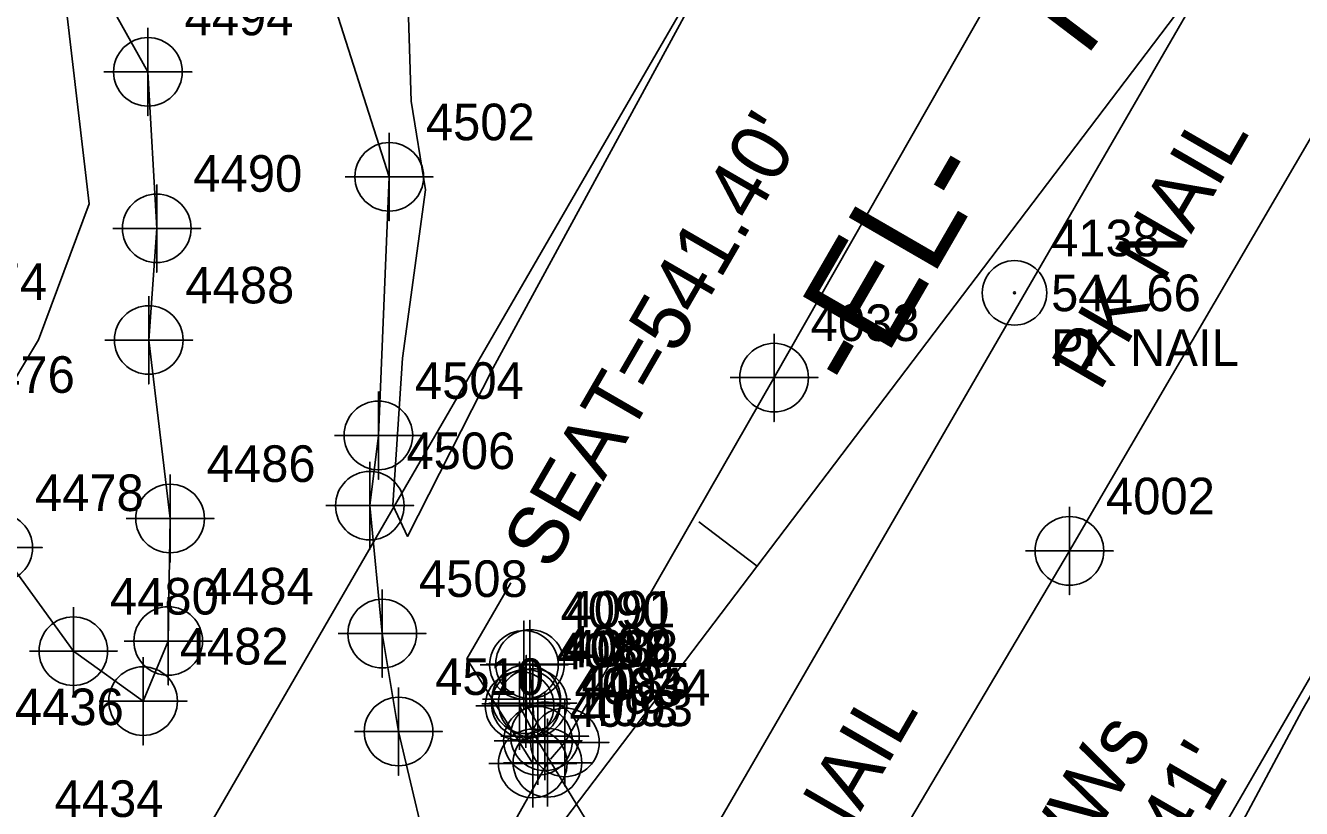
# Model space of a CAD drawing. Extents: x 1653123 to 1656194, y 596584 to 600233.
# Drawn here: x 1653723.1 to 1653810.3, y 598056.2 to 598109.7 of the extents above; entities that cross this region are included whole.
import ezdxf

# ---------------------------------------------------------------- set-up
doc = ezdxf.new("R2010")
doc.units = 0
for name, color, linetype in [('Exist Horizontal Alignment', 7, 'Continuous'), ('Exist Horizontal Alignment Direction Label', 7, 'Continuous'), ('Exist Horizontal Baseline Alignment', 7, 'Continuous'), ('Exist Horizontal Baseline Alignment Direction Label', 7, 'Continuous'), ('Exist Horizontal Baseline Alignment Tick small', 7, 'Continuous'), ('Exist Hydro Jurisdictional Stream or Body of Water', 7, 'Continuous'), ('Exist Hydro Stream or Body of Water Cogo Number', 7, 'Continuous'), ('Exist Property Iron Pin CELL', 7, 'Continuous'), ('Exist Property Iron Pin Cogo Comment', 7, 'Continuous'), ('Exist Property Iron Pin Cogo Elevation', 7, 'Continuous'), ('Exist Property Iron Pin Cogo Number', 7, 'Continuous'), ('Exist Property Iron Pin Text', 7, 'Continuous'), ('Exist Right of Way Line', 7, 'Continuous'), ('Exist Roads EOP Cogo Point CELL', 7, 'Continuous'), ('Exist Structure Major Bridge Seat Top Elevation', 7, 'Continuous'), ('Exist Structure Major Bridge WW Text', 7, 'Continuous'), ('Exist Structure Major Deck Tunnel Box Culvert', 7, 'Continuous'), ('Exist Vegetation Woods Line', 7, 'Continuous'), ('Prop Approach Slab Hatching', 7, 'Continuous'), ('Prop Conc Shoulder Berm Gutter', 7, 'Continuous'), ('Prop Guardrail Anchor Unit CELL', 7, 'Continuous'), ('Prop Horizontal Alignment', 7, 'Continuous'), ('Prop Horizontal Alignment Station Label', 7, 'Continuous'), ('Prop Horizontal Alignment Tick Label', 7, 'Continuous'), ('Prop Horizontal Alignment Tick Large', 7, 'Continuous'), ('Prop Horizontal Alignment Tick Small', 7, 'Continuous'), ('Prop Roadway Bridge', 7, 'Continuous'), ('Prop Superelevation  Arrow CELL', 7, 'Continuous')]:
    doc.layers.add(name, color=color, linetype=linetype)

msp = doc.modelspace()

# ---------------------------------------------------------------- linework, layer by layer
at = {"layer": 'Exist Horizontal Alignment'}
msp.add_line((1653731.562, 597988.043), (1653850.42, 598193.455), dxfattribs=at)
at = {"layer": 'Exist Horizontal Baseline Alignment'}
msp.add_line((1653732.119, 598018.788), (1653909.758, 598252.908), dxfattribs=at)
at = {"layer": 'Exist Horizontal Baseline Alignment Tick small'}
msp.add_line((1653773.109, 598072.811), (1653769.126, 598075.834), dxfattribs=at)
at = {"layer": 'Exist Hydro Jurisdictional Stream or Body of Water'}
for points in [[(1653714.688, 598088.487), (1653716.575, 598082.143), (1653721.284, 598074.065), (1653726.41, 598066.995), (1653731.176, 598063.58), (1653732.89, 598067.686), (1653733.018, 598076.055), (1653731.561, 598088.252), (1653732.108, 598095.882), (1653731.504, 598106.573), (1653726.416, 598115.655), (1653725.798, 598124.414), (1653724.252, 598127.518)], [(1653752.596, 598048.33), (1653751.106, 598051.034), (1653748.622, 598061.502), (1653747.508, 598068.195), (1653746.66, 598076.934), (1653747.243, 598081.733), (1653747.986, 598099.401), (1653743.287, 598114.123), (1653741.057, 598120.621)]]:
    msp.add_lwpolyline(points, dxfattribs=at)
at = {"layer": 'Exist Property Iron Pin CELL'}
for radius in [2.203, 2.203, 0.0707, 0.0707]:
    msp.add_circle((1653790.69, 598091.472), radius, dxfattribs=at)
at = {"layer": 'Exist Right of Way Line'}
for p, q in [((1653705.596, 598003.068), (1653824.453, 598208.48)), ((1653757.529, 597973.018), (1653876.386, 598178.43))]:
    msp.add_line(p, q, dxfattribs=at)
at = {"layer": 'Exist Roads EOP Cogo Point CELL'}
for points in [[(1653774.271, 598088.683), (1653774.271, 598082.683), (1653774.271, 598085.683), (1653777.271, 598085.683), (1653771.271, 598085.683)], [(1653794.44, 598076.843), (1653794.44, 598070.843), (1653794.44, 598073.843), (1653797.44, 598073.843), (1653791.44, 598073.843)], [(1653759.986, 598063.762), (1653759.986, 598057.762), (1653759.986, 598060.762), (1653762.986, 598060.762), (1653756.986, 598060.762)]]:
    msp.add_lwpolyline(points, dxfattribs=at)
for centre in [(1653774.271, 598085.683), (1653794.44, 598073.843), (1653759.986, 598060.762)]:
    msp.add_circle(centre, 2.344, dxfattribs=at)
at = {"layer": 'Exist Structure Major Bridge Seat Top Elevation'}
msp.add_lwpolyline([(1653757.791, 598059.322), (1653753.293, 598066.464), (1653756.299, 598071.656)], dxfattribs=at)
at = {"layer": 'Exist Structure Major Deck Tunnel Box Culvert'}
msp.add_lwpolyline([(1653758.793, 598059.369), (1653737.049, 598020.636)], dxfattribs=at)
at = {"layer": 'Exist Vegetation Woods Line'}
for points in [[(1653589.258, 598252.574), (1653594.936, 598250.375), (1653599.482, 598250.173), (1653605.178, 598250.345), (1653613.312, 598250.888), (1653625.437, 598247.347), (1653631.978, 598239.832), (1653643.705, 598228.37), (1653651.146, 598223.866), (1653661.589, 598219.539), (1653675.876, 598216.138), (1653684.868, 598209.258), (1653690.523, 598202.394), (1653696.352, 598187.358), (1653702.043, 598167.882), (1653707.002, 598150.004), (1653716.092, 598129.888), (1653725.932, 598110.766), (1653727.499, 598097.563), (1653724.039, 598088.274), (1653721.385, 598083.89)], [(1653772.69, 597855.659), (1653780.909, 597872.984), (1653787.83, 597901.293), (1653791.961, 597923.72), (1653796.55, 597945.524), (1653799.728, 597979.56), (1653801.787, 597996.223), (1653796.294, 598010.028), (1653789.109, 598020.31), (1653789.788, 598024.526), (1653810.305, 598062.923), (1653854.435, 598139.764), (1653881.65, 598185.926), (1653890.132, 598190.266), (1653890.781, 598172.436), (1653888.254, 598125.228), (1653881.516, 598039.211), (1653880.393, 597979.917), (1653882.927, 597907.141), (1653887.551, 597812.438), (1653892.774, 597769.351), (1653892.797, 597738.525)], [(1653805.737, 598179.559), (1653755.093, 598086.35), (1653749.238, 598074.838), (1653748.233, 598076.957), (1653748.892, 598087.008), (1653750.469, 598098.506), (1653749.481, 598104.57), (1653748.79, 598126.118)]]:
    msp.add_lwpolyline(points, dxfattribs=at)
at = {"layer": 'Prop Approach Slab Hatching'}
msp.add_lwpolyline([(1653754.791, 598059.322), (1653760.791, 598059.322), (1653757.791, 598059.322), (1653757.791, 598062.322), (1653757.791, 598056.322)], dxfattribs=at)
msp.add_circle((1653757.791, 598059.322), 2.344, dxfattribs=at)
at = {"layer": 'Prop Conc Shoulder Berm Gutter'}
for points in [[(1653963.228, 598414.461), (1653946.12, 598382.228), (1653936.106, 598363.27), (1653937.56, 598362.437), (1653921.881, 598335.541), (1653898.589, 598297.253), (1653874.988, 598257.806), (1653850.996, 598217.569), (1653836.484, 598192.612), (1653818.805, 598162.679), (1653796.343, 598124.457), (1653774.271, 598085.683), (1653759.986, 598060.762), (1653759.005, 598059.616)], [(1653773.15, 598036.351), (1653773.119, 598036.676), (1653772.726, 598037.188), (1653794.44, 598073.843), (1653816.897, 598112.323), (1653839.541, 598150.793), (1653856.887, 598180.317), (1653871.823, 598206.021), (1653894.448, 598243.912), (1653917.39, 598282.615), (1653941.959, 598322.784), (1653953.154, 598342.488), (1653957.769, 598344.372), (1653957.983, 598346.456), (1653959.261, 598348.625), (1653971.076, 598367.128), (1653990.971, 598397.837)]]:
    msp.add_lwpolyline(points, dxfattribs=at)
at = {"layer": 'Prop Guardrail Anchor Unit CELL'}
for points in [[(1653728.504, 598106.573), (1653734.504, 598106.573), (1653731.504, 598106.573), (1653731.504, 598103.573), (1653731.504, 598109.573)], [(1653744.986, 598099.401), (1653750.986, 598099.401), (1653747.986, 598099.401), (1653747.986, 598096.401), (1653747.986, 598102.401)], [(1653729.108, 598095.882), (1653735.108, 598095.882), (1653732.108, 598095.882), (1653732.108, 598092.882), (1653732.108, 598098.882)], [(1653728.561, 598088.252), (1653734.561, 598088.252), (1653731.561, 598088.252), (1653731.561, 598085.252), (1653731.561, 598091.252)], [(1653744.243, 598081.733), (1653750.243, 598081.733), (1653747.243, 598081.733), (1653747.243, 598078.733), (1653747.243, 598084.733)], [(1653743.66, 598076.934), (1653749.66, 598076.934), (1653746.66, 598076.934), (1653746.66, 598073.934), (1653746.66, 598079.934)], [(1653730.018, 598076.055), (1653736.018, 598076.055), (1653733.018, 598076.055), (1653733.018, 598073.055), (1653733.018, 598079.055)], [(1653718.284, 598074.065), (1653724.284, 598074.065), (1653721.284, 598074.065), (1653721.284, 598071.065), (1653721.284, 598077.065)], [(1653744.508, 598068.195), (1653750.508, 598068.195), (1653747.508, 598068.195), (1653747.508, 598065.195), (1653747.508, 598071.195)], [(1653729.89, 598067.686), (1653735.89, 598067.686), (1653732.89, 598067.686), (1653732.89, 598064.686), (1653732.89, 598070.686)], [(1653723.41, 598066.995), (1653729.41, 598066.995), (1653726.41, 598066.995), (1653726.41, 598063.995), (1653726.41, 598069.995)], [(1653728.176, 598063.58), (1653734.176, 598063.58), (1653731.176, 598063.58), (1653731.176, 598060.58), (1653731.176, 598066.58)], [(1653745.622, 598061.502), (1653751.622, 598061.502), (1653748.622, 598061.502), (1653748.622, 598058.502), (1653748.622, 598064.502)]]:
    msp.add_lwpolyline(points, dxfattribs=at)
for centre in [(1653731.504, 598106.573), (1653747.986, 598099.401), (1653732.108, 598095.882), (1653731.561, 598088.252), (1653747.243, 598081.733), (1653746.66, 598076.934), (1653733.018, 598076.055), (1653721.284, 598074.065), (1653747.508, 598068.195), (1653726.41, 598066.995), (1653732.89, 598067.686), (1653731.176, 598063.58), (1653748.622, 598061.502)]:
    msp.add_circle(centre, 2.344, dxfattribs=at)
at = {"layer": 'Prop Horizontal Alignment Station Label'}
for points in [[(1653754.189, 598066.056), (1653760.189, 598066.056), (1653757.189, 598066.056), (1653757.189, 598069.056), (1653757.189, 598063.056)], [(1653754.599, 598066.11), (1653760.599, 598066.11), (1653757.599, 598066.11), (1653757.599, 598069.11), (1653757.599, 598063.11)], [(1653754.346, 598063.707), (1653760.346, 598063.707), (1653757.346, 598063.707), (1653757.346, 598066.707), (1653757.346, 598060.707)], [(1653753.891, 598063.257), (1653759.891, 598063.257), (1653756.891, 598063.257), (1653756.891, 598066.257), (1653756.891, 598060.257)], [(1653754.317, 598063.393), (1653760.317, 598063.393), (1653757.317, 598063.393), (1653757.317, 598066.393), (1653757.317, 598060.393)], [(1653754.786, 598063.45), (1653760.786, 598063.45), (1653757.786, 598063.45), (1653757.786, 598066.45), (1653757.786, 598060.45)], [(1653755.615, 598061.178), (1653761.615, 598061.178), (1653758.615, 598061.178), (1653758.615, 598064.178), (1653758.615, 598058.178)], [(1653755.145, 598060.87), (1653761.145, 598060.87), (1653758.145, 598060.87), (1653758.145, 598063.87), (1653758.145, 598057.87)]]:
    msp.add_lwpolyline(points, dxfattribs=at)
for centre in [(1653757.599, 598066.11), (1653757.189, 598066.056), (1653757.346, 598063.707), (1653756.891, 598063.257), (1653757.317, 598063.393), (1653757.786, 598063.45), (1653758.145, 598060.87), (1653758.615, 598061.178)]:
    msp.add_circle(centre, 2.344, dxfattribs=at)
at = {"layer": 'Prop Horizontal Alignment Tick Large'}
msp.add_lwpolyline([(1653755.793, 598059.369), (1653761.793, 598059.369), (1653758.793, 598059.369), (1653758.793, 598062.369), (1653758.793, 598056.369)], dxfattribs=at)
msp.add_circle((1653758.793, 598059.369), 2.344, dxfattribs=at)
at = {"layer": 'Prop Superelevation  Arrow CELL'}
for points in [[(1653757.374, 598063.296), (1653757.189, 598066.056), (1653757.599, 598066.11), (1653757.855, 598062.474)], [(1653758.615, 598061.178), (1653757.317, 598063.393), (1653756.891, 598063.257), (1653758.145, 598060.87), (1653773.584, 598035.496)]]:
    msp.add_lwpolyline(points, dxfattribs=at)

# ---------------------------------------------------------------- texts
at = {"layer": 'Exist Horizontal Alignment Direction Label'}
msp.add_text('-EL-', height=7, rotation=59.9451, dxfattribs=at).set_placement((1653780.36, 598084.356))
at = {"layer": 'Exist Horizontal Baseline Alignment Direction Label'}
msp.add_text('N 37%%d 11\' 22.0" E', height=7, rotation=52.81055, dxfattribs=at).set_placement((1653795.468, 598107.415))
at = {"layer": 'Exist Hydro Stream or Body of Water Cogo Number'}
for s, p in [('4494', (1653734.004, 598109.073)), ('4502', (1653750.486, 598101.901)), ('4490', (1653734.608, 598098.382)), ('4474', (1653717.188, 598090.987)), ('4488', (1653734.061, 598090.752)), ('4476', (1653719.075, 598084.643)), ('4504', (1653749.743, 598084.233)), ('4506', (1653749.16, 598079.434)), ('4486', (1653735.518, 598078.555)), ('4478', (1653723.784, 598076.565)), ('4508', (1653750.008, 598070.696)), ('4480', (1653728.91, 598069.495)), ('4484', (1653735.39, 598070.186)), ('4482', (1653733.676, 598066.08)), ('4510', (1653751.122, 598064.002)), ('4436', (1653722.421, 598061.94)), ('4434', (1653725.132, 598055.665))]:
    msp.add_text(s, height=2.5, dxfattribs=at).set_placement(p)
at = {"layer": 'Exist Property Iron Pin Cogo Comment'}
msp.add_text('PK NAIL', height=2.5, dxfattribs=at).set_placement((1653793.19, 598086.472))
at = {"layer": 'Exist Property Iron Pin Cogo Elevation'}
msp.add_text('544.66', height=2.5, dxfattribs=at).set_placement((1653793.19, 598090.222))
at = {"layer": 'Exist Property Iron Pin Cogo Number'}
msp.add_text('4138', height=2.5, dxfattribs=at).set_placement((1653793.19, 598093.972))
msp.add_text('4138', height=2.5, dxfattribs=at).set_placement((1653793.19, 598093.972))
at = {"layer": 'Exist Property Iron Pin Text'}
for p in [(1653796.495, 598084.644), (1653773.912, 598045.186)]:
    msp.add_text('PK NAIL', height=4, rotation=59.9255, dxfattribs=at).set_placement(p)
at = {"layer": 'Exist Structure Major Bridge Seat Top Elevation'}
for s, p in [("SEAT=541.40'", (1653759.032, 598072.385)), ("SEAT=541.41'", (1653788.578, 598029.391))]:
    msp.add_text(s, height=4, rotation=59.9255, dxfattribs=at).set_placement(p)
at = {"layer": 'Exist Structure Major Bridge WW Text'}
msp.add_text('WOOD WWs', height=4, rotation=59.92548, dxfattribs=at).set_placement((1653784.39, 598033.916))
at = {"layer": 'Prop Horizontal Alignment'}
for s, p in [('4033', (1653776.771, 598088.183)), ('4002', (1653796.94, 598076.343)), ('4034', (1653762.486, 598063.262))]:
    msp.add_text(s, height=2.5, dxfattribs=at).set_placement(p)
at = {"layer": 'Prop Horizontal Alignment Tick Label'}
for s, p in [('4090', (1653759.689, 598068.556)), ('4091', (1653760.099, 598068.61)), ('4089', (1653759.846, 598066.207)), ('4088', (1653760.286, 598065.95)), ('4087', (1653759.391, 598065.757)), ('4086', (1653759.817, 598065.893)), ('4084', (1653760.645, 598063.37)), ('4085', (1653761.115, 598063.679))]:
    msp.add_text(s, height=2.5, dxfattribs=at).set_placement(p)
at = {"layer": 'Prop Horizontal Alignment Tick Small'}
msp.add_text('4093', height=2.5, dxfattribs=at).set_placement((1653761.293, 598061.869))
at = {"layer": 'Prop Roadway Bridge'}
msp.add_text('4098', height=2.5, dxfattribs=at).set_placement((1653760.291, 598061.822))

doc.saveas('drawing.dxf')
